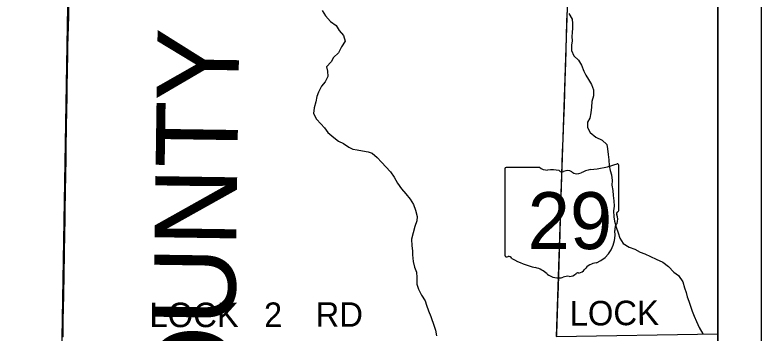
# Model space of a CAD drawing. Extents: x -11.1 to 34, y -3.9 to 22.
# Drawn here: x 7.271 to 9, y 17.295 to 18.032 of the extents above; entities that cross this region are included whole.
import ezdxf

# ---------------------------------------------------------------- set-up
doc = ezdxf.new("R2010")
doc.units = 0
for name, color, linetype in [('GM_X_Corporation', 7, 'Continuous'), ('GM_X_County_Road', 7, 'Continuous'), ('GM_X_County_Road_Text', 7, 'Continuous'), ('GM_X_County_Text', 7, 'Continuous'), ('GM_X_Minor_River', 7, 'Continuous'), ('GM_X_State_Location', 7, 'Continuous'), ('GM_X_State_Route', 7, 'Continuous'), ('GM_X_State_Shield', 7, 'Continuous'), ('GM_X_Township_Road', 7, 'Continuous'), ('GM_X_Township_Road_Text', 7, 'Continuous'), ('SH_Data', 7, 'Continuous')]:
    doc.layers.add(name, color=color, linetype=linetype)

msp = doc.modelspace()

# ---------------------------------------------------------------- linework, layer by layer
at = {"layer": 'GM_X_Corporation'}
for points in [[(8.9, 14.1), (8.9, 19.2515)], [(8.9, 15.2587), (8.9, 19.2515)], [(7.3961, 18.1012), (7.3946, 18.0285), (7.393, 17.9583), (7.3926, 17.9353), (7.3919, 17.9061), (7.3914, 17.8608), (7.3912, 17.844), (7.3904, 17.8067), (7.3897, 17.7756), (7.3893, 17.7582), (7.3891, 17.7365), (7.3886, 17.693), (7.3881, 17.6657), (7.3875, 17.6166), (7.3868, 17.5836), (7.3864, 17.5607), (7.3857, 17.5209), (7.3852, 17.4836), (7.3842, 17.4258), (7.3835, 17.3873), (7.3825, 17.3475), (7.3821, 17.3289), (7.3817, 17.2858)], [(7.3817, 17.2858), (7.3821, 17.3289), (7.3825, 17.3475), (7.3835, 17.3873), (7.3842, 17.4258), (7.3852, 17.4836), (7.3857, 17.5209), (7.3864, 17.5607), (7.3868, 17.5836), (7.3875, 17.6166), (7.3881, 17.6657), (7.3886, 17.693), (7.3891, 17.7365), (7.3893, 17.7582), (7.3897, 17.7756), (7.3904, 17.8067), (7.3912, 17.844), (7.3914, 17.8608), (7.3919, 17.9061), (7.3926, 17.9353), (7.393, 17.9583), (7.3946, 18.0285), (7.3961, 18.1012)], [(7.3817, 17.2858), (7.3821, 17.3289), (7.3825, 17.3475), (7.3835, 17.3873), (7.3842, 17.4258), (7.3852, 17.4836), (7.3857, 17.5209), (7.3864, 17.5607), (7.3868, 17.5836), (7.3875, 17.6166), (7.3881, 17.6657), (7.3886, 17.693), (7.3891, 17.7365), (7.3893, 17.7582), (7.3897, 17.7756), (7.3904, 17.8067), (7.3912, 17.844), (7.3914, 17.8608), (7.3919, 17.9061), (7.3926, 17.9353), (7.393, 17.9583), (7.3946, 18.0285), (7.3961, 18.1012)], [(7.3961, 18.1012), (7.3946, 18.0285), (7.393, 17.9583), (7.3926, 17.9353), (7.3919, 17.9061), (7.3914, 17.8608), (7.3912, 17.844), (7.3904, 17.8067), (7.3897, 17.7756), (7.3893, 17.7582), (7.3891, 17.7365), (7.3886, 17.693), (7.3881, 17.6657), (7.3875, 17.6166), (7.3868, 17.5836), (7.3864, 17.5607), (7.3857, 17.5209), (7.3852, 17.4836), (7.3842, 17.4258), (7.3835, 17.3873), (7.3825, 17.3475), (7.3821, 17.3289), (7.3817, 17.2858)]]:
    msp.add_lwpolyline(points, dxfattribs=at)
for points in [[(6.3851, 18.2506), (7.3955, 18.2326), (7.3797, 17.2828), (7.3791, 17.2313), (6.3727, 17.2765), (6.3791, 18.2511)], [(8.9, 17.2929), (8.9, 18.2314), (8.569, 18.2332), (8.5569, 18.2331), (8.525, 17.2867)]]:
    msp.add_lwpolyline(points, close=True, dxfattribs=at)
at = {"layer": 'GM_X_County_Road'}
msp.add_lwpolyline([(7.3819, 17.2853), (7.3824, 17.3284), (7.3828, 17.347), (7.3832, 17.3656), (7.3835, 17.3762), (7.3837, 17.3867), (7.3841, 17.4054), (7.3843, 17.4153), (7.3845, 17.4253), (7.3851, 17.4625), (7.3852, 17.4728), (7.3854, 17.4831), (7.3857, 17.5017), (7.3858, 17.511), (7.3859, 17.5203), (7.3866, 17.5601), (7.3871, 17.5831), (7.3874, 17.5996), (7.3877, 17.616), (7.388, 17.6347), (7.3882, 17.6499), (7.3884, 17.6651), (7.3888, 17.6925), (7.3893, 17.736), (7.3894, 17.7468), (7.3896, 17.7577), (7.3899, 17.7751), (7.3902, 17.7906), (7.3906, 17.8062), (7.391, 17.8248), (7.3914, 17.8434), (7.3916, 17.8602), (7.392, 17.8922), (7.3922, 17.9056), (7.3928, 17.9348), (7.393, 17.9463), (7.3932, 17.9578), (7.3941, 17.995), (7.3945, 18.0115), (7.3948, 18.028), (7.396, 18.0829)], dxfattribs=at)
at = {"layer": 'GM_X_Minor_River'}
for points in [[(7.9827, 18.042), (7.9908, 18.0297), (8.0024, 18.0165), (8.0152, 18.0072), (8.0226, 17.9952), (8.0323, 17.9836), (8.0359, 17.971), (8.0276, 17.9579), (8.0209, 17.9435), (8.0092, 17.9331), (8.0037, 17.9229), (7.9928, 17.9114), (7.9949, 17.9014), (7.9958, 17.8892), (7.9895, 17.8764), (7.9813, 17.8663), (7.9741, 17.8524), (7.9705, 17.8426), (7.968, 17.8301), (7.9643, 17.8164), (7.9629, 17.8035), (7.9699, 17.7901), (7.98, 17.7792), (7.9879, 17.7696), (7.9961, 17.7592), (8.01, 17.7479), (8.0205, 17.7393), (8.0319, 17.7334), (8.0443, 17.7255), (8.0541, 17.7208), (8.0636, 17.7191), (8.0762, 17.7166), (8.0891, 17.7144), (8.0986, 17.7112), (8.1103, 17.7015), (8.1204, 17.6902), (8.1413, 17.6678), (8.1499, 17.6555), (8.1576, 17.642), (8.1665, 17.6285), (8.177, 17.6169), (8.1871, 17.6049), (8.1945, 17.5922), (8.1992, 17.5796), (8.2028, 17.5647), (8.2026, 17.5544), (8.1977, 17.5412), (8.194, 17.5264), (8.1896, 17.5124), (8.1904, 17.4968), (8.1921, 17.485), (8.1923, 17.4755), (8.194, 17.4606), (8.1968, 17.4472), (8.2011, 17.4354), (8.2024, 17.4232), (8.2021, 17.4076), (8.2061, 17.3965), (8.2131, 17.3826), (8.2213, 17.3692), (8.2245, 17.3588), (8.2289, 17.3462), (8.2347, 17.3328), (8.2427, 17.3105), (8.2452, 17.301), (8.248, 17.2884)], [(8.5546, 18.035), (8.5624, 18.0216), (8.5626, 18.012), (8.5632, 18.0006), (8.5622, 17.9911), (8.5617, 17.9816), (8.5619, 17.9717), (8.5605, 17.9615), (8.5603, 17.9493), (8.5662, 17.9371), (8.577, 17.9266), (8.5841, 17.9154), (8.5892, 17.9016), (8.5936, 17.892), (8.5999, 17.882), (8.6073, 17.8701), (8.6113, 17.8579), (8.6118, 17.8445), (8.6081, 17.8313), (8.6071, 17.8176), (8.6057, 17.8051), (8.6028, 17.7926), (8.5976, 17.7828), (8.5974, 17.771), (8.6037, 17.7591), (8.6172, 17.7486), (8.6316, 17.7411), (8.6425, 17.7317), (8.6438, 17.7215), (8.6459, 17.7085), (8.6472, 17.6955), (8.648, 17.6818), (8.6505, 17.6715), (8.6534, 17.6608), (8.655, 17.6478), (8.6545, 17.6372), (8.6561, 17.625), (8.6571, 17.6132), (8.6584, 17.601), (8.6593, 17.5884), (8.6583, 17.5774), (8.6588, 17.5637), (8.6605, 17.5534), (8.6645, 17.5396), (8.6688, 17.5266), (8.6728, 17.5143), (8.6806, 17.5024), (8.6945, 17.4938), (8.7074, 17.489), (8.7199, 17.4823), (8.7305, 17.4779), (8.7434, 17.4716), (8.7566, 17.466), (8.7721, 17.4588), (8.7853, 17.4491), (8.798, 17.4359), (8.809, 17.4277), (8.8186, 17.4134), (8.8229, 17.3993), (8.8262, 17.3882), (8.829, 17.3786), (8.8323, 17.3687), (8.8359, 17.3591), (8.8402, 17.3453), (8.845, 17.3334), (8.8501, 17.3212), (8.8563, 17.3073), (8.8648, 17.2927)]]:
    msp.add_lwpolyline(points, dxfattribs=at)
at = {"layer": 'GM_X_State_Route'}
msp.add_lwpolyline([(8.5501, 18.0371), (8.5484, 17.9861), (8.5473, 17.947), (8.5457, 17.8986), (8.5451, 17.8806), (8.5445, 17.852), (8.5433, 17.8216), (8.5418, 17.7868), (8.5413, 17.7663), (8.5406, 17.7433), (8.5394, 17.7148), (8.5386, 17.6868), (8.5367, 17.639), (8.5361, 17.6204), (8.5344, 17.5626), (8.5333, 17.5228), (8.5321, 17.4812), (8.5304, 17.4278), (8.5297, 17.4017), (8.5284, 17.367), (8.5272, 17.3371), (8.5266, 17.3204), (8.5258, 17.2886)], dxfattribs=at)
at = {"layer": 'GM_X_State_Shield'}
for p, q in [((8.4064, 17.675), (8.4064, 17.4749)), ((8.4862, 17.6784), (8.409, 17.6784)), ((8.6701, 17.5787), (8.6701, 17.6834)), ((8.67, 17.5787), (8.6701, 17.5787))]:
    msp.add_line(p, q, dxfattribs=at)
for centre, radius, start, end in [((8.4094, 17.6754), 0.00305, 98.1301, 188.1301), ((8.5046, 17.7017), 0.0296, 231.6195, 271.1119), ((8.5144, 17.5661), 0.1064, 80.4867, 94.9883), ((8.6118, 17.6173), 0.0563, 97.3462, 120.7689), ((8.5761, 17.9513), 0.2796, 275.8445, 288.9065), ((8.6671, 17.6838), 0.00294, 351.8621, 97.738), ((8.5386, 17.6764), 0.00855, 219.7921, 297.1024), ((8.5511, 17.6533), 0.0178, 54.4667, 119.1411), ((8.574, 17.685), 0.0214, 233.8562, 294.8282), ((8.6694, 17.571), 0.00454, 107.944, 210.337), ((8.6405, 17.5578), 0.0273, 340.033, 23.6496), ((8.6669, 17.5783), 0.00314, 289.6038, 7.7341), ((8.6806, 17.5349), 0.0198, 136.8065, 186.9296), ((8.5918, 17.5216), 0.0699, 292.3089, 8.9858), ((8.4094, 17.4744), 0.00308, 171.9584, 258.3066), ((8.4099, 17.4949), 0.0235, 267.339, 280.6039), ((8.4147, 17.4633), 0.00848, 29.7484, 93.2717), ((8.5218, 17.6431), 0.2019, 240.4129, 257.1985), ((8.6213, 17.4187), 0.0383, 94.4031, 142.5768), ((8.4616, 17.385), 0.0632, 47.1842, 75.836), ((8.5299, 17.4623), 0.0401, 230.7004, 286.2918), ((8.556, 17.4473), 0.0214, 268.777, 315.5493), ((8.5753, 17.428), 0.00601, 65.7517, 132.6484), ((8.5728, 17.4555), 0.0226, 282.8732, 323.2771), ((8.5531, 17.3931), 0.0329, 85.6951, 111.2099)]:
    msp.add_arc(centre, radius, start, end, dxfattribs=at)
at = {"layer": 'GM_X_Township_Road'}
msp.add_lwpolyline([(7.3819, 17.2853), (7.3824, 17.3284), (7.3828, 17.347), (7.3832, 17.3656), (7.3835, 17.3762), (7.3837, 17.3867), (7.3841, 17.4054), (7.3843, 17.4153), (7.3845, 17.4253), (7.3851, 17.4625), (7.3852, 17.4728), (7.3854, 17.4831), (7.3857, 17.5017), (7.3858, 17.511), (7.3859, 17.5203), (7.3866, 17.5601), (7.3871, 17.5831), (7.3874, 17.5996), (7.3877, 17.616), (7.388, 17.6347), (7.3882, 17.6499), (7.3884, 17.6651), (7.3888, 17.6925), (7.3893, 17.736), (7.3894, 17.7468), (7.3896, 17.7577), (7.3899, 17.7751), (7.3902, 17.7906), (7.3906, 17.8062), (7.391, 17.8248), (7.3914, 17.8434), (7.3916, 17.8602), (7.392, 17.8922), (7.3922, 17.9056), (7.3928, 17.9348), (7.393, 17.9463), (7.3932, 17.9578), (7.3941, 17.995), (7.3945, 18.0115), (7.3948, 18.028), (7.396, 18.0829)], dxfattribs=at)
at = {"layer": 'SH_Data'}
for p, q in [((9, 21), (9, 14)), ((8.9, 20.9), (8.9, 14.1))]:
    msp.add_line(p, q, dxfattribs=at)

# ---------------------------------------------------------------- texts
at = {"layer": 'GM_X_County_Road_Text'}
for s, height, rotation, p in [('LOCK', 0.05682, 0, (7.5826, 17.3082)), ('2', 0.0568, 1.1098, (7.8487, 17.3082)), ('RD', 0.05682, 0, (7.9676, 17.3091))]:
    msp.add_text(s, height=height, rotation=rotation, dxfattribs=at).set_placement(p)
at = {"layer": 'GM_X_County_Text'}
msp.add_text('SHELBY COUNTY', height=0.189394, rotation=89.1576, dxfattribs=at).set_placement((7.7595, 15.8606))
at = {"layer": 'GM_X_State_Location'}
for s in ['s', 'r']:
    msp.add_text(s, height=0.000189, dxfattribs=at).set_placement((8.5352, 17.5616))
msp.add_text('29', height=0.000189, rotation=0, dxfattribs=at).set_placement((8.4876, 17.5478))
at = {"layer": 'GM_X_State_Shield'}
msp.add_text('29', height=0.13184, dxfattribs=at).set_placement((8.459, 17.489))
at = {"layer": 'GM_X_Township_Road_Text'}
msp.add_text('LOCK', height=0.05682, rotation=0.499, dxfattribs=at).set_placement((8.5566, 17.3116))

doc.saveas('drawing.dxf')
